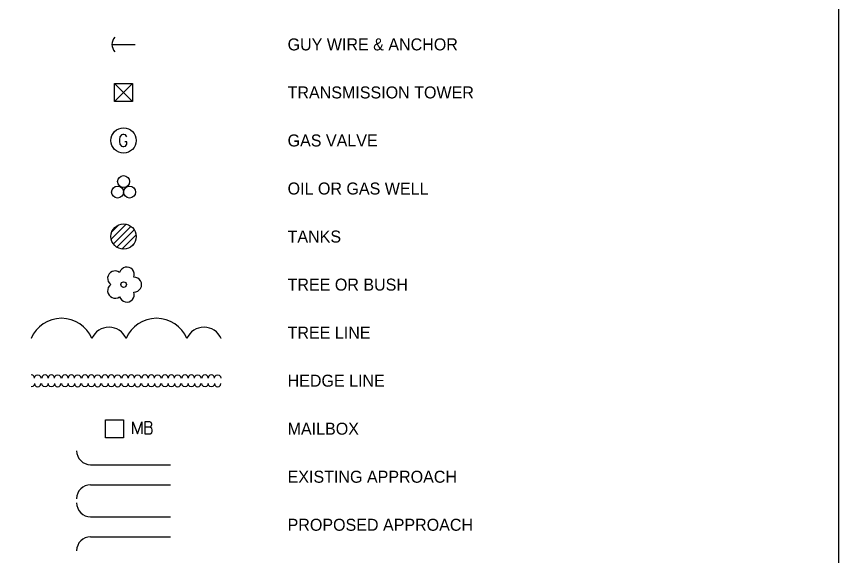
# Model space of a CAD drawing. Extents: x 49991.4 to 50021, y 49987.6 to 50011.4.
# Drawn here: x 50012.64 to 50016.75, y 49993.461 to 49996.155 of the extents above; entities that cross this region are included whole.
import ezdxf

# ---------------------------------------------------------------- set-up
doc = ezdxf.new("R2010")
doc.units = 0
doc.layers.add('Level 1', color=7, linetype='Continuous')
doc.layers.add('Level 2', color=7, linetype='Continuous')

msp = doc.modelspace()

# ---------------------------------------------------------------- linework, layer by layer
at = {"layer": 'Level 1'}
for p, q in [((50013.117, 49996.0152), (50013.2336, 49996.0152)), ((50013.2203, 49995.8202), (50013.1303, 49995.7302)), ((50013.1303, 49995.8202), (50013.2203, 49995.7302)), ((50013.1303, 49995.8202), (50013.2203, 49995.8202)), ((50013.1303, 49995.7302), (50013.1303, 49995.8202)), ((50013.2203, 49995.8202), (50013.2203, 49995.7302)), ((50013.2203, 49995.7302), (50013.1303, 49995.7302)), ((50013.171, 49995.5647), (50013.1648, 49995.5629)), ((50013.1766, 49995.5647), (50013.171, 49995.5647)), ((50013.1842, 49995.5629), (50013.1766, 49995.5647)), ((50013.1568, 49995.5529), (50013.1549, 49995.5402)), ((50013.1549, 49995.5402), (50013.1549, 49995.5303)), ((50013.1549, 49995.5303), (50013.1573, 49995.5161)), ((50013.1648, 49995.5629), (50013.1568, 49995.5529)), ((50013.1922, 49995.5284), (50013.1818, 49995.5284)), ((50013.1922, 49995.5529), (50013.1842, 49995.5629)), ((50013.1922, 49995.5166), (50013.1922, 49995.5284)), ((50013.1573, 49995.5161), (50013.1643, 49995.5066)), ((50013.1643, 49995.5066), (50013.1714, 49995.5047)), ((50013.1714, 49995.5047), (50013.1766, 49995.5047)), ((50013.1766, 49995.5047), (50013.1842, 49995.5066)), ((50013.1842, 49995.5066), (50013.1922, 49995.5166)), ((50013.1139, 49995.042), (50013.1886, 49995.1167)), ((50013.1173, 49995.0794), (50013.1512, 49995.1133)), ((50013.1243, 49995.0185), (50013.212, 49995.1062)), ((50013.1418, 49995.0021), (50013.2285, 49995.0888)), ((50013.1666, 49994.9929), (50013.2376, 49995.0639)), ((50013.2115, 49995.0039), (50013.2267, 49995.0191)), ((50012.7126, 49994.5452), (50012.7126, 49994.5452)), ((50013.1876, 49994.5452), (50013.1876, 49994.5452)), ((50013.1876, 49994.5452), (50013.1876, 49994.5452)), ((50013.1876, 49994.5452), (50013.1876, 49994.5452)), ((50013.6626, 49994.5452), (50013.6626, 49994.5452)), ((50013.6626, 49994.5452), (50013.6626, 49994.5452)), ((50012.714, 49994.3641), (50012.7126, 49994.3637)), ((50012.722, 49994.362), (50012.714, 49994.3641)), ((50012.7278, 49994.3561), (50012.722, 49994.362)), ((50012.7298, 49994.3482), (50012.7278, 49994.3561)), ((50012.7298, 49994.3481), (50012.7319, 49994.3561)), ((50012.7319, 49994.3561), (50012.7377, 49994.3619)), ((50012.7377, 49994.3619), (50012.7456, 49994.3641)), ((50012.7456, 49994.3641), (50012.7535, 49994.3619)), ((50012.7535, 49994.3619), (50012.7593, 49994.3561)), ((50012.7593, 49994.3561), (50012.7614, 49994.3481)), ((50012.7688, 49994.3561), (50012.7667, 49994.3481)), ((50012.7745, 49994.3619), (50012.7688, 49994.3561)), ((50012.7825, 49994.3641), (50012.7745, 49994.3619)), ((50012.7904, 49994.3619), (50012.7825, 49994.3641)), ((50012.7961, 49994.3561), (50012.7904, 49994.3619)), ((50012.7982, 49994.3481), (50012.7961, 49994.3561)), ((50012.8003, 49994.3561), (50012.7982, 49994.3481)), ((50012.8061, 49994.3619), (50012.8003, 49994.3561)), ((50012.814, 49994.3641), (50012.8061, 49994.3619)), ((50012.822, 49994.3619), (50012.814, 49994.3641)), ((50012.8278, 49994.3561), (50012.822, 49994.3619)), ((50012.8298, 49994.3481), (50012.8278, 49994.3561)), ((50012.8298, 49994.3481), (50012.8319, 49994.3561)), ((50012.8319, 49994.3561), (50012.8377, 49994.3619)), ((50012.8377, 49994.3619), (50012.8456, 49994.3641)), ((50012.8456, 49994.3641), (50012.8535, 49994.3619)), ((50012.8535, 49994.3619), (50012.8593, 49994.3561)), ((50012.8593, 49994.3561), (50012.8614, 49994.3481)), ((50012.8688, 49994.3561), (50012.8667, 49994.3481)), ((50012.8745, 49994.3619), (50012.8688, 49994.3561)), ((50012.8825, 49994.3641), (50012.8745, 49994.3619)), ((50012.8904, 49994.3619), (50012.8825, 49994.3641)), ((50012.8961, 49994.3561), (50012.8904, 49994.3619)), ((50012.8982, 49994.3481), (50012.8961, 49994.3561)), ((50012.9003, 49994.3561), (50012.8982, 49994.3481)), ((50012.9061, 49994.3619), (50012.9003, 49994.3561)), ((50012.914, 49994.3641), (50012.9061, 49994.3619)), ((50012.922, 49994.3619), (50012.914, 49994.3641)), ((50012.9278, 49994.3561), (50012.922, 49994.3619)), ((50012.9298, 49994.3481), (50012.9278, 49994.3561)), ((50012.9298, 49994.3481), (50012.9319, 49994.3561)), ((50012.9319, 49994.3561), (50012.9377, 49994.3619)), ((50012.9377, 49994.3619), (50012.9456, 49994.3641)), ((50012.9456, 49994.3641), (50012.9535, 49994.3619)), ((50012.9535, 49994.3619), (50012.9593, 49994.3561)), ((50012.9593, 49994.3561), (50012.9614, 49994.3481)), ((50012.9688, 49994.3561), (50012.9667, 49994.3481)), ((50012.9745, 49994.3619), (50012.9688, 49994.3561)), ((50012.9825, 49994.3641), (50012.9745, 49994.3619)), ((50012.9904, 49994.3619), (50012.9825, 49994.3641)), ((50012.9961, 49994.3561), (50012.9904, 49994.3619)), ((50012.9982, 49994.3481), (50012.9961, 49994.3561)), ((50013.0003, 49994.3561), (50012.9982, 49994.3481)), ((50013.0061, 49994.3619), (50013.0003, 49994.3561)), ((50013.014, 49994.3641), (50013.0061, 49994.3619)), ((50013.022, 49994.3619), (50013.014, 49994.3641)), ((50013.0278, 49994.3561), (50013.022, 49994.3619)), ((50013.0298, 49994.3481), (50013.0278, 49994.3561)), ((50013.0298, 49994.3481), (50013.0319, 49994.3561)), ((50013.0319, 49994.3561), (50013.0377, 49994.3619)), ((50013.0377, 49994.3619), (50013.0456, 49994.3641)), ((50013.0456, 49994.3641), (50013.0535, 49994.3619)), ((50013.0535, 49994.3619), (50013.0593, 49994.3561)), ((50013.0593, 49994.3561), (50013.0614, 49994.3481)), ((50013.0688, 49994.3561), (50013.0667, 49994.3481)), ((50013.0745, 49994.3619), (50013.0688, 49994.3561)), ((50013.0825, 49994.3641), (50013.0745, 49994.3619)), ((50013.0904, 49994.3619), (50013.0825, 49994.3641)), ((50013.0961, 49994.3561), (50013.0904, 49994.3619)), ((50013.0982, 49994.3481), (50013.0961, 49994.3561)), ((50013.1003, 49994.3561), (50013.0982, 49994.3481)), ((50013.1061, 49994.3619), (50013.1003, 49994.3561)), ((50013.114, 49994.3641), (50013.1061, 49994.3619)), ((50013.122, 49994.3619), (50013.114, 49994.3641)), ((50013.1278, 49994.3561), (50013.122, 49994.3619)), ((50013.1298, 49994.3481), (50013.1278, 49994.3561)), ((50013.1298, 49994.3481), (50013.1319, 49994.3561)), ((50013.1319, 49994.3561), (50013.1377, 49994.3619)), ((50013.1377, 49994.3619), (50013.1456, 49994.3641)), ((50013.1456, 49994.3641), (50013.1535, 49994.3619)), ((50013.1535, 49994.3619), (50013.1593, 49994.3561)), ((50013.1593, 49994.3561), (50013.1614, 49994.3481)), ((50013.1688, 49994.3561), (50013.1667, 49994.3481)), ((50013.1745, 49994.3619), (50013.1688, 49994.3561)), ((50013.1825, 49994.3641), (50013.1745, 49994.3619)), ((50013.1904, 49994.3619), (50013.1825, 49994.3641)), ((50013.1961, 49994.3561), (50013.1904, 49994.3619)), ((50013.1982, 49994.3481), (50013.1961, 49994.3561)), ((50013.2003, 49994.3561), (50013.1982, 49994.3481)), ((50013.2061, 49994.3619), (50013.2003, 49994.3561)), ((50013.214, 49994.3641), (50013.2061, 49994.3619)), ((50013.222, 49994.3619), (50013.214, 49994.3641)), ((50013.2278, 49994.3561), (50013.222, 49994.3619)), ((50013.2298, 49994.3481), (50013.2278, 49994.3561)), ((50013.2298, 49994.3481), (50013.2319, 49994.3561)), ((50013.2319, 49994.3561), (50013.2377, 49994.3619)), ((50013.2377, 49994.3619), (50013.2456, 49994.3641)), ((50013.2456, 49994.3641), (50013.2535, 49994.3619)), ((50013.2535, 49994.3619), (50013.2593, 49994.3561)), ((50013.2593, 49994.3561), (50013.2614, 49994.3481)), ((50013.2688, 49994.3561), (50013.2667, 49994.3481)), ((50013.2745, 49994.3619), (50013.2688, 49994.3561)), ((50013.2825, 49994.3641), (50013.2745, 49994.3619)), ((50013.2904, 49994.3619), (50013.2825, 49994.3641)), ((50013.2961, 49994.3561), (50013.2904, 49994.3619)), ((50013.2982, 49994.3481), (50013.2961, 49994.3561)), ((50013.3003, 49994.3561), (50013.2982, 49994.3481)), ((50013.3061, 49994.3619), (50013.3003, 49994.3561)), ((50013.314, 49994.3641), (50013.3061, 49994.3619)), ((50013.322, 49994.3619), (50013.314, 49994.3641)), ((50013.3278, 49994.3561), (50013.322, 49994.3619)), ((50013.3298, 49994.3481), (50013.3278, 49994.3561)), ((50013.3298, 49994.3481), (50013.3319, 49994.3561)), ((50013.3319, 49994.3561), (50013.3377, 49994.3619)), ((50013.3377, 49994.3619), (50013.3456, 49994.3641)), ((50013.3456, 49994.3641), (50013.3535, 49994.3619)), ((50013.3535, 49994.3619), (50013.3593, 49994.3561)), ((50013.3593, 49994.3561), (50013.3614, 49994.3481)), ((50013.3688, 49994.3561), (50013.3667, 49994.3481)), ((50013.3745, 49994.3619), (50013.3688, 49994.3561)), ((50013.3825, 49994.3641), (50013.3745, 49994.3619)), ((50013.3904, 49994.3619), (50013.3825, 49994.3641)), ((50013.3961, 49994.3561), (50013.3904, 49994.3619)), ((50013.3982, 49994.3481), (50013.3961, 49994.3561)), ((50013.4003, 49994.3561), (50013.3982, 49994.3481)), ((50013.4061, 49994.3619), (50013.4003, 49994.3561)), ((50013.414, 49994.3641), (50013.4061, 49994.3619)), ((50013.422, 49994.3619), (50013.414, 49994.3641)), ((50013.4278, 49994.3561), (50013.422, 49994.3619)), ((50013.4298, 49994.3481), (50013.4278, 49994.3561)), ((50013.4298, 49994.3481), (50013.4319, 49994.3561)), ((50013.4319, 49994.3561), (50013.4377, 49994.3619)), ((50013.4377, 49994.3619), (50013.4456, 49994.3641)), ((50013.4456, 49994.3641), (50013.4535, 49994.3619)), ((50013.4535, 49994.3619), (50013.4593, 49994.3561)), ((50013.4593, 49994.3561), (50013.4614, 49994.3481)), ((50013.4688, 49994.3561), (50013.4667, 49994.3481)), ((50013.4745, 49994.3619), (50013.4688, 49994.3561)), ((50013.4825, 49994.3641), (50013.4745, 49994.3619)), ((50013.4904, 49994.3619), (50013.4825, 49994.3641)), ((50013.4961, 49994.3561), (50013.4904, 49994.3619)), ((50013.4982, 49994.3481), (50013.4961, 49994.3561)), ((50013.5003, 49994.3561), (50013.4982, 49994.3481)), ((50013.5061, 49994.3619), (50013.5003, 49994.3561)), ((50013.514, 49994.3641), (50013.5061, 49994.3619)), ((50013.522, 49994.3619), (50013.514, 49994.3641)), ((50013.5278, 49994.3561), (50013.522, 49994.3619)), ((50013.5298, 49994.3481), (50013.5278, 49994.3561)), ((50013.5298, 49994.3481), (50013.5319, 49994.3561)), ((50013.5319, 49994.3561), (50013.5377, 49994.3619)), ((50013.5377, 49994.3619), (50013.5456, 49994.3641)), ((50013.5456, 49994.3641), (50013.5535, 49994.3619)), ((50013.5535, 49994.3619), (50013.5593, 49994.3561)), ((50013.5593, 49994.3561), (50013.5614, 49994.3481)), ((50013.5688, 49994.3561), (50013.5667, 49994.3481)), ((50013.5745, 49994.3619), (50013.5688, 49994.3561)), ((50013.5825, 49994.3641), (50013.5745, 49994.3619)), ((50013.5904, 49994.3619), (50013.5825, 49994.3641)), ((50013.5961, 49994.3561), (50013.5904, 49994.3619)), ((50013.5982, 49994.3481), (50013.5961, 49994.3561)), ((50013.6003, 49994.3561), (50013.5982, 49994.3481)), ((50013.6061, 49994.3619), (50013.6003, 49994.3561)), ((50013.614, 49994.3641), (50013.6061, 49994.3619)), ((50013.622, 49994.3619), (50013.614, 49994.3641)), ((50013.6278, 49994.3561), (50013.622, 49994.3619)), ((50013.6298, 49994.3481), (50013.6278, 49994.3561)), ((50013.6298, 49994.3481), (50013.6319, 49994.3561)), ((50013.6319, 49994.3561), (50013.6377, 49994.3619)), ((50013.6377, 49994.3619), (50013.6456, 49994.3641)), ((50013.6456, 49994.3641), (50013.6535, 49994.3619)), ((50013.6535, 49994.3619), (50013.6593, 49994.3561)), ((50013.6593, 49994.3561), (50013.6614, 49994.3481)), ((50012.714, 49994.3046), (50012.7126, 49994.305)), ((50012.722, 49994.3067), (50012.714, 49994.3046)), ((50012.7278, 49994.3126), (50012.722, 49994.3067)), ((50012.7298, 49994.3205), (50012.7278, 49994.3126)), ((50012.7298, 49994.3205), (50012.7319, 49994.3125)), ((50012.7319, 49994.3125), (50012.7377, 49994.3067)), ((50012.7377, 49994.3067), (50012.7456, 49994.3045)), ((50012.7456, 49994.3045), (50012.7535, 49994.3067)), ((50012.7535, 49994.3067), (50012.7593, 49994.3125)), ((50012.7593, 49994.3125), (50012.7614, 49994.3205)), ((50012.7688, 49994.3125), (50012.7667, 49994.3205)), ((50012.7745, 49994.3067), (50012.7688, 49994.3125)), ((50012.7825, 49994.3045), (50012.7745, 49994.3067)), ((50012.7904, 49994.3067), (50012.7825, 49994.3045)), ((50012.7961, 49994.3125), (50012.7904, 49994.3067)), ((50012.7982, 49994.3205), (50012.7961, 49994.3125)), ((50012.8003, 49994.3125), (50012.7982, 49994.3205)), ((50012.8061, 49994.3067), (50012.8003, 49994.3125)), ((50012.814, 49994.3045), (50012.8061, 49994.3067)), ((50012.822, 49994.3067), (50012.814, 49994.3045)), ((50012.8278, 49994.3125), (50012.822, 49994.3067)), ((50012.8298, 49994.3205), (50012.8278, 49994.3125)), ((50012.8298, 49994.3205), (50012.8319, 49994.3125)), ((50012.8319, 49994.3125), (50012.8377, 49994.3067)), ((50012.8377, 49994.3067), (50012.8456, 49994.3045)), ((50012.8456, 49994.3045), (50012.8535, 49994.3067)), ((50012.8535, 49994.3067), (50012.8593, 49994.3125)), ((50012.8593, 49994.3125), (50012.8614, 49994.3205)), ((50012.8688, 49994.3125), (50012.8667, 49994.3205)), ((50012.8745, 49994.3067), (50012.8688, 49994.3125)), ((50012.8825, 49994.3045), (50012.8745, 49994.3067)), ((50012.8904, 49994.3067), (50012.8825, 49994.3045)), ((50012.8961, 49994.3125), (50012.8904, 49994.3067)), ((50012.8982, 49994.3205), (50012.8961, 49994.3125)), ((50012.9003, 49994.3125), (50012.8982, 49994.3205)), ((50012.9061, 49994.3067), (50012.9003, 49994.3125)), ((50012.914, 49994.3045), (50012.9061, 49994.3067)), ((50012.922, 49994.3067), (50012.914, 49994.3045)), ((50012.9278, 49994.3125), (50012.922, 49994.3067)), ((50012.9298, 49994.3205), (50012.9278, 49994.3125)), ((50012.9298, 49994.3205), (50012.9319, 49994.3125)), ((50012.9319, 49994.3125), (50012.9377, 49994.3067)), ((50012.9377, 49994.3067), (50012.9456, 49994.3045)), ((50012.9456, 49994.3045), (50012.9535, 49994.3067)), ((50012.9535, 49994.3067), (50012.9593, 49994.3125)), ((50012.9593, 49994.3125), (50012.9614, 49994.3205)), ((50012.9688, 49994.3125), (50012.9667, 49994.3205)), ((50012.9745, 49994.3067), (50012.9688, 49994.3125)), ((50012.9825, 49994.3045), (50012.9745, 49994.3067)), ((50012.9904, 49994.3067), (50012.9825, 49994.3045)), ((50012.9961, 49994.3125), (50012.9904, 49994.3067)), ((50012.9982, 49994.3205), (50012.9961, 49994.3125)), ((50013.0003, 49994.3125), (50012.9982, 49994.3205)), ((50013.0061, 49994.3067), (50013.0003, 49994.3125)), ((50013.014, 49994.3045), (50013.0061, 49994.3067)), ((50013.022, 49994.3067), (50013.014, 49994.3045)), ((50013.0278, 49994.3125), (50013.022, 49994.3067)), ((50013.0298, 49994.3205), (50013.0278, 49994.3125)), ((50013.0298, 49994.3205), (50013.0319, 49994.3125)), ((50013.0319, 49994.3125), (50013.0377, 49994.3067)), ((50013.0377, 49994.3067), (50013.0456, 49994.3045)), ((50013.0456, 49994.3045), (50013.0535, 49994.3067)), ((50013.0535, 49994.3067), (50013.0593, 49994.3125)), ((50013.0593, 49994.3125), (50013.0614, 49994.3205)), ((50013.0688, 49994.3125), (50013.0667, 49994.3205)), ((50013.0745, 49994.3067), (50013.0688, 49994.3125)), ((50013.0825, 49994.3045), (50013.0745, 49994.3067)), ((50013.0904, 49994.3067), (50013.0825, 49994.3045)), ((50013.0961, 49994.3125), (50013.0904, 49994.3067)), ((50013.0982, 49994.3205), (50013.0961, 49994.3125)), ((50013.1003, 49994.3125), (50013.0982, 49994.3205)), ((50013.1061, 49994.3067), (50013.1003, 49994.3125)), ((50013.114, 49994.3045), (50013.1061, 49994.3067)), ((50013.122, 49994.3067), (50013.114, 49994.3045)), ((50013.1278, 49994.3125), (50013.122, 49994.3067)), ((50013.1298, 49994.3205), (50013.1278, 49994.3125)), ((50013.1298, 49994.3205), (50013.1319, 49994.3125)), ((50013.1319, 49994.3125), (50013.1377, 49994.3067)), ((50013.1377, 49994.3067), (50013.1456, 49994.3045)), ((50013.1456, 49994.3045), (50013.1535, 49994.3067)), ((50013.1535, 49994.3067), (50013.1593, 49994.3125)), ((50013.1593, 49994.3125), (50013.1614, 49994.3205)), ((50013.1688, 49994.3125), (50013.1667, 49994.3205)), ((50013.1745, 49994.3067), (50013.1688, 49994.3125)), ((50013.1825, 49994.3045), (50013.1745, 49994.3067)), ((50013.1904, 49994.3067), (50013.1825, 49994.3045)), ((50013.1961, 49994.3125), (50013.1904, 49994.3067)), ((50013.1982, 49994.3205), (50013.1961, 49994.3125)), ((50013.2003, 49994.3125), (50013.1982, 49994.3205)), ((50013.2061, 49994.3067), (50013.2003, 49994.3125)), ((50013.214, 49994.3045), (50013.2061, 49994.3067)), ((50013.222, 49994.3067), (50013.214, 49994.3045)), ((50013.2278, 49994.3125), (50013.222, 49994.3067)), ((50013.2298, 49994.3205), (50013.2278, 49994.3125)), ((50013.2298, 49994.3205), (50013.2319, 49994.3125)), ((50013.2319, 49994.3125), (50013.2377, 49994.3067)), ((50013.2377, 49994.3067), (50013.2456, 49994.3045)), ((50013.2456, 49994.3045), (50013.2535, 49994.3067)), ((50013.2535, 49994.3067), (50013.2593, 49994.3125)), ((50013.2593, 49994.3125), (50013.2614, 49994.3205)), ((50013.2688, 49994.3125), (50013.2667, 49994.3205)), ((50013.2745, 49994.3067), (50013.2688, 49994.3125)), ((50013.2825, 49994.3045), (50013.2745, 49994.3067)), ((50013.2904, 49994.3067), (50013.2825, 49994.3045)), ((50013.2961, 49994.3125), (50013.2904, 49994.3067)), ((50013.2982, 49994.3205), (50013.2961, 49994.3125)), ((50013.3003, 49994.3125), (50013.2982, 49994.3205)), ((50013.3061, 49994.3067), (50013.3003, 49994.3125)), ((50013.314, 49994.3045), (50013.3061, 49994.3067)), ((50013.322, 49994.3067), (50013.314, 49994.3045)), ((50013.3278, 49994.3125), (50013.322, 49994.3067)), ((50013.3298, 49994.3205), (50013.3278, 49994.3125)), ((50013.3298, 49994.3205), (50013.3319, 49994.3125)), ((50013.3319, 49994.3125), (50013.3377, 49994.3067)), ((50013.3377, 49994.3067), (50013.3456, 49994.3045)), ((50013.3456, 49994.3045), (50013.3535, 49994.3067)), ((50013.3535, 49994.3067), (50013.3593, 49994.3125)), ((50013.3593, 49994.3125), (50013.3614, 49994.3205)), ((50013.3688, 49994.3125), (50013.3667, 49994.3205)), ((50013.3745, 49994.3067), (50013.3688, 49994.3125)), ((50013.3825, 49994.3045), (50013.3745, 49994.3067)), ((50013.3904, 49994.3067), (50013.3825, 49994.3045)), ((50013.3961, 49994.3125), (50013.3904, 49994.3067)), ((50013.3982, 49994.3205), (50013.3961, 49994.3125)), ((50013.4003, 49994.3125), (50013.3982, 49994.3205)), ((50013.4061, 49994.3067), (50013.4003, 49994.3125)), ((50013.414, 49994.3045), (50013.4061, 49994.3067)), ((50013.422, 49994.3067), (50013.414, 49994.3045)), ((50013.4278, 49994.3125), (50013.422, 49994.3067)), ((50013.4298, 49994.3205), (50013.4278, 49994.3125)), ((50013.4298, 49994.3205), (50013.4319, 49994.3125)), ((50013.4319, 49994.3125), (50013.4377, 49994.3067)), ((50013.4377, 49994.3067), (50013.4456, 49994.3045)), ((50013.4456, 49994.3045), (50013.4535, 49994.3067)), ((50013.4535, 49994.3067), (50013.4593, 49994.3125)), ((50013.4593, 49994.3125), (50013.4614, 49994.3205)), ((50013.4688, 49994.3125), (50013.4667, 49994.3205)), ((50013.4745, 49994.3067), (50013.4688, 49994.3125)), ((50013.4825, 49994.3045), (50013.4745, 49994.3067)), ((50013.4904, 49994.3067), (50013.4825, 49994.3045)), ((50013.4961, 49994.3125), (50013.4904, 49994.3067)), ((50013.4982, 49994.3205), (50013.4961, 49994.3125)), ((50013.5003, 49994.3125), (50013.4982, 49994.3205)), ((50013.5061, 49994.3067), (50013.5003, 49994.3125)), ((50013.514, 49994.3045), (50013.5061, 49994.3067)), ((50013.522, 49994.3067), (50013.514, 49994.3045)), ((50013.5278, 49994.3125), (50013.522, 49994.3067)), ((50013.5298, 49994.3205), (50013.5278, 49994.3125)), ((50013.5298, 49994.3205), (50013.5319, 49994.3125)), ((50013.5319, 49994.3125), (50013.5377, 49994.3067)), ((50013.5377, 49994.3067), (50013.5456, 49994.3045)), ((50013.5456, 49994.3045), (50013.5535, 49994.3067)), ((50013.5535, 49994.3067), (50013.5593, 49994.3125)), ((50013.5593, 49994.3125), (50013.5614, 49994.3205)), ((50013.5688, 49994.3125), (50013.5667, 49994.3205)), ((50013.5745, 49994.3067), (50013.5688, 49994.3125)), ((50013.5825, 49994.3045), (50013.5745, 49994.3067)), ((50013.5904, 49994.3067), (50013.5825, 49994.3045)), ((50013.5961, 49994.3125), (50013.5904, 49994.3067)), ((50013.5982, 49994.3205), (50013.5961, 49994.3125)), ((50013.6003, 49994.3125), (50013.5982, 49994.3205)), ((50013.6061, 49994.3067), (50013.6003, 49994.3125)), ((50013.614, 49994.3045), (50013.6061, 49994.3067)), ((50013.622, 49994.3067), (50013.614, 49994.3045)), ((50013.6278, 49994.3125), (50013.622, 49994.3067)), ((50013.6298, 49994.3205), (50013.6278, 49994.3125)), ((50013.6298, 49994.3205), (50013.6319, 49994.3125)), ((50013.6319, 49994.3125), (50013.6377, 49994.3067)), ((50013.6377, 49994.3067), (50013.6456, 49994.3045)), ((50013.6456, 49994.3045), (50013.6535, 49994.3067)), ((50013.6535, 49994.3067), (50013.6593, 49994.3125)), ((50013.6593, 49994.3125), (50013.6614, 49994.3205)), ((50013.0853, 49994.0502), (50013.0853, 49994.1402)), ((50013.0853, 49994.1402), (50013.1753, 49994.1402)), ((50013.1753, 49994.1402), (50013.1753, 49994.0502)), ((50013.2216, 49994.0702), (50013.2216, 49994.1302)), ((50013.2216, 49994.1302), (50013.2443, 49994.0702)), ((50013.2443, 49994.0702), (50013.266, 49994.1302)), ((50013.266, 49994.1302), (50013.266, 49994.0702)), ((50013.3057, 49994.1302), (50013.2816, 49994.1302)), ((50013.2816, 49994.1302), (50013.2816, 49994.0702)), ((50013.3137, 49994.126), (50013.3057, 49994.1302)), ((50013.3161, 49994.118), (50013.3137, 49994.126)), ((50013.3085, 49994.1028), (50013.2816, 49994.1028)), ((50013.3085, 49994.1028), (50013.3137, 49994.1085)), ((50013.3161, 49994.0967), (50013.3085, 49994.1028)), ((50013.3137, 49994.1085), (50013.3161, 49994.1156)), ((50013.3161, 49994.1156), (50013.3161, 49994.118)), ((50013.3189, 49994.0896), (50013.3161, 49994.0967)), ((50013.3189, 49994.0825), (50013.3189, 49994.0896)), ((50013.1753, 49994.0502), (50013.0853, 49994.0502)), ((50013.2816, 49994.0702), (50013.3085, 49994.0702)), ((50013.3085, 49994.0702), (50013.3161, 49994.0745)), ((50013.3161, 49994.0745), (50013.3189, 49994.0825)), ((50013.0103, 49993.9152), (50013.4103, 49993.9152)), ((50013.0103, 49993.8152), (50013.4103, 49993.8152)), ((50013.0103, 49993.6552), (50013.4103, 49993.6552)), ((50013.0103, 49993.5552), (50013.4103, 49993.5552))]:
    msp.add_line(p, q, dxfattribs=at)
msp.add_lwpolyline([(49999.3835, 49998.9992), (50016.7501, 49998.9992), (50016.7501, 49987.7988), (49999.3835, 49987.7988)], close=True, dxfattribs=at)
for centre, radius in [((50013.1753, 49995.5352), 0.0632), ((50013.1754, 49995.3296), 0.03), ((50013.1454, 49995.2776), 0.03), ((50013.2054, 49995.2776), 0.03), ((50013.1753, 49995.0553), 0.0631), ((50013.1753, 49994.8153), 0.0139)]:
    msp.add_circle(centre, radius, dxfattribs=at)
for centre, radius, start, end in [((50013.1688, 49996.0152), 0.0518, 135, 225), ((50012.8648, 49994.4819), 0.1648, 22.6224, 157.3788), ((50013.3398, 49994.4819), 0.1648, 22.6224, 157.3788), ((50013.1025, 49994.5096), 0.0927, 22.6224, 157.3788), ((50013.5775, 49994.5096), 0.0927, 22.6224, 157.3788), ((50013.0103, 49993.9852), 0.07, 180, 270), ((50013.0103, 49993.7452), 0.07, 90, 180), ((50013.0103, 49993.7252), 0.07, 180, 270), ((50013.0103, 49993.4852), 0.07, 90, 180)]:
    msp.add_arc(centre, radius, start, end, dxfattribs=at)
for centre, major_axis, ratio, start_param, end_param in [((50013.1913, 49994.8643), (0.0119, 0.0365), 0.976256, 4.712389, 7.853982), ((50013.1336, 49994.8456), (0.0311, -0.0226), 0.976328, 1.570796, 4.712389), ((50013.2269, 49994.8152), (-0.0384, 0), 0.976553, 1.570796, 4.712389), ((50013.1335, 49994.7849), (0.0311, 0.0226), 0.976564, 1.570796, 4.712389), ((50013.1912, 49994.7662), (-0.0118, 0.0365), 0.976277, 1.570796, 4.712389)]:
    msp.add_ellipse(centre, major_axis=major_axis, ratio=ratio, start_param=start_param, end_param=end_param, dxfattribs=at)

# ---------------------------------------------------------------- texts
at = {"layer": 'Level 2'}
for s, height, p in [('GUY WIRE & ANCHOR                       ', 0.059999, (50013.9953, 49995.9852)), ('TRANSMISSION TOWER                      ', 0.059999, (50013.9953, 49995.7452)), ('GAS VALVE                                 ', 0.06, (50013.9953, 49995.5052)), ('OIL OR GAS WELL                         ', 0.059999, (50013.9953, 49995.2652)), ('TANKS                                   ', 0.059999, (50013.9953, 49995.0252)), ('TREE OR BUSH        ', 0.059999, (50013.9953, 49994.7852)), ('TREE LINE                               ', 0.059999, (50013.9953, 49994.5452)), ('HEDGE LINE                              ', 0.059999, (50013.9953, 49994.3052)), ('MAILBOX                                ', 0.06, (50013.9953, 49994.0652)), ('EXISTING APPROACH   ', 0.059999, (50013.9953, 49993.8252)), ('PROPOSED APPROACH   ', 0.059999, (50013.9953, 49993.5852))]:
    msp.add_text(s, height=height, dxfattribs=at).set_placement(p)

doc.saveas('drawing.dxf')
